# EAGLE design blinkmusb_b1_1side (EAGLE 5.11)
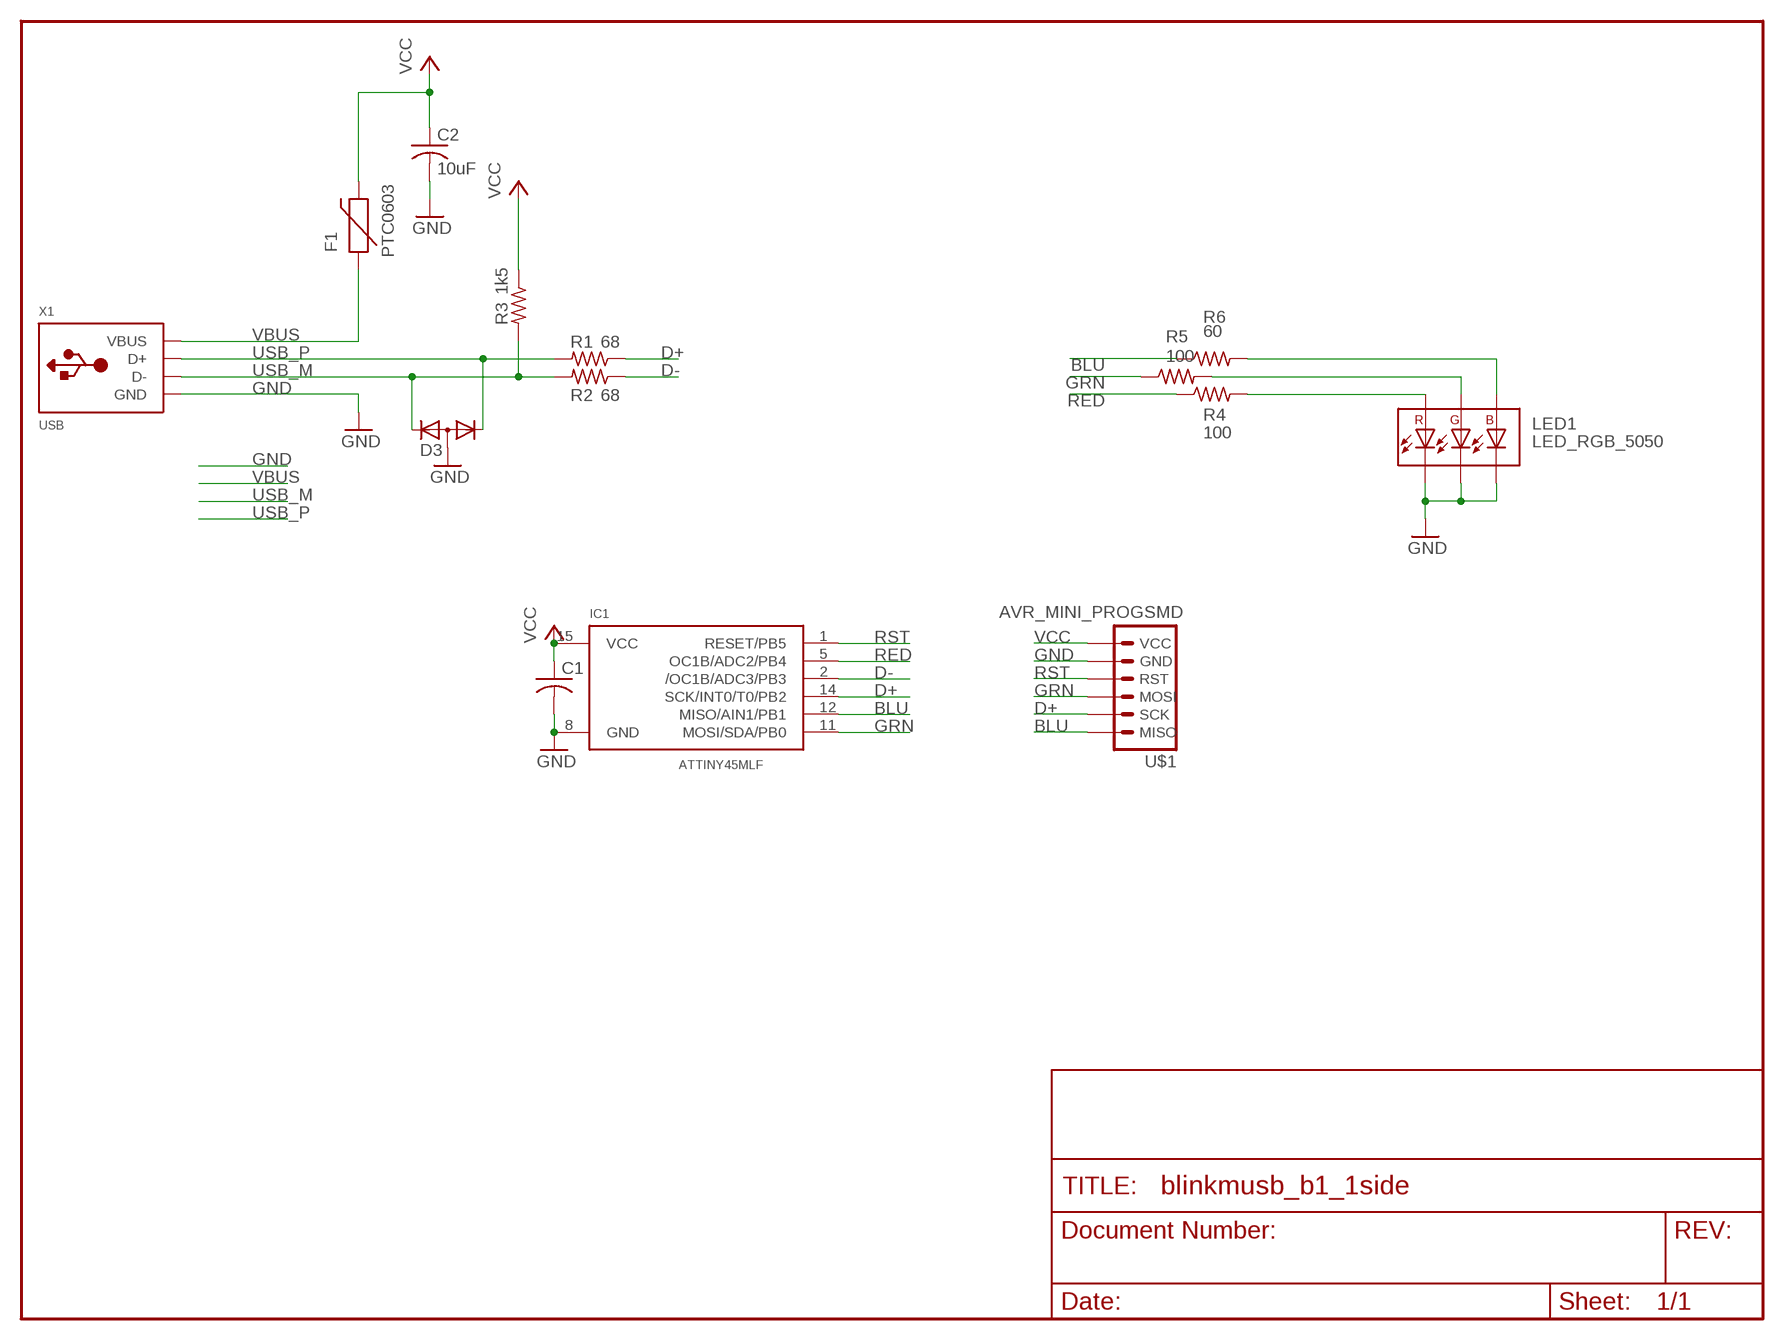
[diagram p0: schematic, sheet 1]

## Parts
C1  C-USC0603  [C0603]
C2  10uF  C-USC0805  [C0805]
D3  DIODE-2CA|ACSOT23  [SOT23]
F1  PTC0603  [0603]
IC1  ATTINY45MLF  [MLF20]
LED1  LED_RGB_5050  [LED_5050]
R1  68  R-US_R0603  [R0603]
R2  68  R-US_R0603  [R0603]
R3  1k5  R-US_R0603  [R0603]
R4  100  R-US_R0603  [R0603]
R5  100  R-US_R0603  [R0603]
R6  60  R-US_R0603  [R0603]
U$1  AVR_MINI_PROGSMD  [AVR_MINI_PROG]
X1  USB  [MOLEX-48037-1000]

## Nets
BLU: IC1.12(MISO/AIN1/PB1) R6.1 U$1.6(MISO)
D+: IC1.14(SCK/INT0/T0/PB2) R1.1 U$1.5(SCK)
D-: IC1.2(/OC1B/ADC3/PB3) R2.1
GND: C1.2 C2.2 D3.3(A) IC1.8(GND) LED1.P$4(C2) LED1.P$5(C1) LED1.P$6(C0) U$1.2(GND) X1.4(GND)
GRN: IC1.11(MOSI/SDA/PB0) R5.1 U$1.4(MOSI)
RBLU: LED1.P$3(A2) R6.2
RED: IC1.5(OC1B/ADC2/PB4) R4.1
RGRN: LED1.P$2(A1) R5.2
RRED: LED1.P$1(A0) R4.2
RST: IC1.1(RESET/PB5) U$1.3(RST)
USB_M: D3.2(K2) R2.2 R3.2 X1.2(D-)
USB_P: D3.1(K1) R1.2 X1.3(D+)
VBUS: F1.1 X1.1(VBUS)
VCC: C1.1 C2.1 F1.2 IC1.15(VCC) R3.1 U$1.1(VCC)

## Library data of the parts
C1 C2 = rcl:C-US: CAPACITOR, American symbol
D3 = diode:DIODE-2CA|AC: Dual DIODE Cathode-Anode|Anode-Cathode
F1 = SparkFun-20110517:PTC: Resettable Fuse PTC
IC1 = todstuff:ATTINY45
LED1 = todstuff:LED_RGB_5050
R1-R6 = rcl:R-US_: RESISTOR, American symbol
U$1 = SparkFun-20110517:AVR_MINI_PROG
X1 = todstuff:USB

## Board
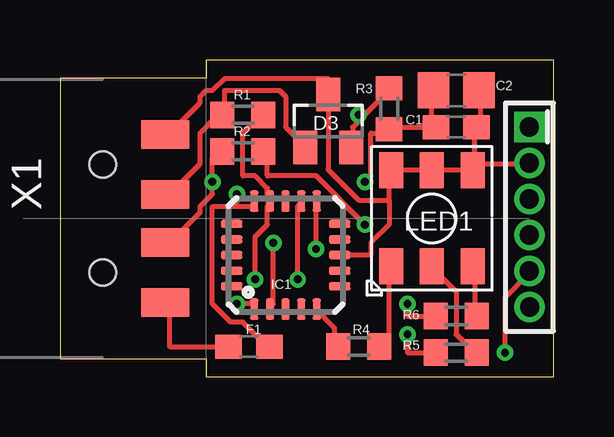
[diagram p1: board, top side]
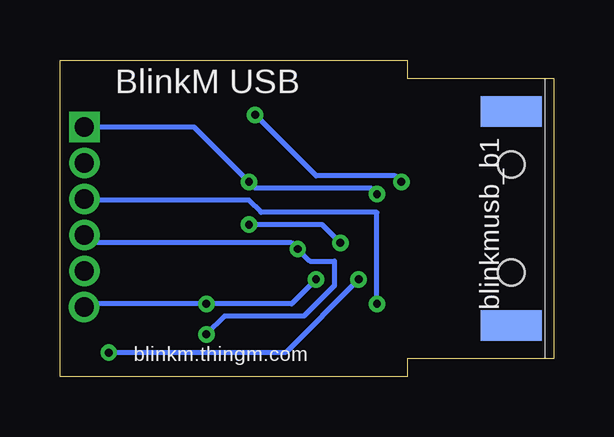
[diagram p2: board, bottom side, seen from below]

Size 20.57 x 13.21 mm. Coordinates in mm from the lower left corner, seen from the top.
Outline: 0,0.76 6.1,0.76 6.1,0 20.57,0 20.57,0.76 20.57,12.45 20.57,13.21 13.72,13.21 6.1,13.21 6.1,12.45 0,12.45 0,0.76
Copper layers (1*16): Top 0.0356mm / dielectric 1.5011mm / Bottom 0.0356mm
Design rules "LaenPCBOrder *": minimum track width 8mil, minimum drill 13mil, track to track 6mil, track to pad 8mil, pad to pad 8mil, via to via 8mil, smd to smd 6mil, copper to edge 15mil, drill to drill 8mil, minimum pad ring 7mil, minimum via ring 7mil, stop-mask expansion 4mil, vias tented up to drill 25mil, thermal gap 10mil
tRestrict: area -6.6,0 to 3.6,12.7
bRestrict: area -6.6,0 to 3.6,12.7

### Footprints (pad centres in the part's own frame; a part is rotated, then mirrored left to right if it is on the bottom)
C0603 = smd 1.1 x 1: 1 -0.85,0; 2 0.85,0
C0805 = smd 1.3 x 1.5: 1 -0.95,0; 2 0.95,0
SOT23 = smd 1 x 1.4: 1 -0.95,-1.1; 2 0.95,-1.1; 3 0,1.1
0603 = smd 1.1 x 1: 1 -0.85,0; 2 0.85,0
MLF20 = smd 0.9 x 0.35: 1 -2.25,1.3; 2 -2.25,0.65; 3 -2.25,0; 4 -2.25,-0.65; 5 -2.25,-1.3; 11 2.25,-1.3; 12 2.25,-0.65; 13 2.25,0; 14 2.25,0.65; 15 2.25,1.3 | smd 0.35 x 0.9: 6 -1.3,-2.25; 7 -0.65,-2.25; 8 0,-2.25; 9 0.65,-2.25; 10 1.3,-2.25; 16 1.3,2.25; 17 0.65,2.25; 18 0,2.25; 19 -0.65,2.25; 20 -1.3,2.25
LED_5050 = smd 1 x 1.5: P$1 1.7,2; P$2 0,2; P$3 -1.7,2; P$4 -1.7,-2; P$5 0,-2; P$6 1.7,-2
R0603 = smd 1 x 1.1: 1 -0.85,0; 2 0.85,0
AVR_MINI_PROG = drill 0.8 pad 1.27 square: 1 0,0 | drill 0.8 pad 1.27 round: 2 1.5,0; 3 3,0; 4 4.5,0; 5 6,0; 6 7.5,0.01
MOLEX-48037-1000 = smd 2 x 1.2: 1 2.6,-3.5; 2 2.6,-1; 3 2.6,1; 4 2.6,3.5 | smd 2.54 x 1.27 bottom: P$1 0,4.45; P$2 0,-4.45 | hole 1.1: 0,2.25; 0,-2.25

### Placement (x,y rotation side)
C1  16.51,10.41 0 top
C2  16.51,11.94 0 top
D3  11.18,10.67 0 top
F1  7.87,1.27 0 top
IC1  9.4,5.08 90 top
LED1  15.49,6.6 180 top
R1  7.62,10.92 180 top
R2  7.62,9.4 180 top
R3  13.72,11.18 90 top
R4  12.45,1.27 0 top
R5  16.51,1.02 0 top
R6  16.51,2.54 0 top
U$1  19.56,10.41 270 top
X1  1.78,6.6 0 top

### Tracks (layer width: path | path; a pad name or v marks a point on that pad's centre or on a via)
BLU  (via drill 0.33)
  Top 0.203: v9.91,4.06 9.91,7.11 IC1.12 | v14.48,3.05 14.48,2.54 15.49,2.54 R6.1
  Bottom 0.203: v9.91,4.06 10.92,3.05 v14.48,3.05 19.56,3.05 U$1.6
D+  (via drill 0.33)
  Top 0.203: R1.1 8.38,10.92 7.62,10.16 7.62,8.38 8.13,8.38 8.64,7.87 8.64,7.37 IC1.14 8.64,7.11 8.64,6.35 8.13,5.84 v8.13,4.06 | v18.54,1.02 18.54,3.3 19.56,4.32 U$1.5
  Bottom 0.203: v8.13,4.06 11.18,1.02 v18.54,1.02
D-  (via drill 0.33)
  Top 0.203: v8.89,5.59 8.89,3.05 IC1.2 | v12.7,6.35 10.67,8.38 8.64,8.38 8.64,9.4 R2.1
  Bottom 0.203: v8.89,5.59 9.65,6.35 v12.7,6.35
GND
  Top 0.203: C2.2 17.53,11.94 17.53,10.41 C1.2 17.27,10.41 17.27,8.89 | 13.72,7.37 13.72,8.38 LED1.P$6 13.97,8.64 15.49,8.64 | 13.72,7.37 13.72,6.35 12.95,5.59 12.95,5.08 11.68,5.08 IC1.8 | 13.72,7.37 12.45,7.37 11.18,8.64 11.18,11.68 D3.3 11.18,11.94 11.18,12.45 6.86,12.45 6.35,11.94 6.1,11.94 5.84,11.68 5.84,11.43 4.57,10.16 X1.4 | 15.49,8.64 LED1.P$5 15.49,8.64 | 15.49,8.64 17.02,8.64 LED1.P$4 | 17.27,8.89 17.27,8.64 LED1.P$4 | 17.27,8.89 19.56,8.89 U$1.2 | LED1.P$4 17.27,8.89
GRN  (via drill 0.33)
  Top 0.203: v10.67,5.33 10.67,7.11 IC1.11 | v14.48,1.78 14.48,1.02 15.49,1.02 R5.1
  Bottom 0.203: U$1.4 19.56,5.84 19.3,5.59 10.92,5.59 v10.67,5.33 10.16,4.83 9.14,4.83 9.14,3.81 10.41,2.54 13.72,2.54 v14.48,1.78
RBLU
  Top 0.203: R6.2 17.27,2.54 17.27,4.57 LED1.P$3
RED
  Top 0.203: IC1.5 10.67,2.79 11.43,2.03 11.43,1.27 R4.1
RGRN
  Top 0.203: R5.2 17.27,1.02 16.51,1.78 16.51,3.56 15.49,4.57 LED1.P$2
RRED
  Top 0.203: R4.2 13.46,1.27 13.72,1.52 13.72,4.57 LED1.P$1
RST  (via drill 0.33)
  Top 0.203: v7.37,3.05 8.13,3.05 IC1.1
  Bottom 0.203: v7.37,3.05 7.37,6.86 12.19,6.86 12.7,7.37 19.56,7.37 U$1.3
USB_M  (via drill 0.33)
  Top 0.203: 12.7,10.92 12.19,10.41 12.19,9.65 D3.2 | 12.7,10.92 13.72,11.94 R3.2 | R2.2 6.6,9.4 6.35,9.14 v6.35,8.13 6.35,7.62 5.84,7.11 5.84,6.86 4.57,5.59 X1.2 | v12.45,10.92 12.7,10.92
  Bottom 0.203: v12.45,10.92 9.91,8.38 6.6,8.38 v6.35,8.13
USB_P
  Top 0.203: X1.3 4.57,7.62 5.84,8.89 5.84,10.16 6.6,10.92 R1.2 6.86,10.92 6.86,11.94 9.14,11.94 9.4,11.68 9.4,10.41 10.16,9.65 D3.1
VBUS
  Top 0.203: F1.1 6.86,1.27 4.57,1.27 4.57,3.05 X1.1
VCC  (via drill 0.33)
  Top 0.203: 7.37,7.11 6.35,7.11 6.35,3.05 7.11,2.29 7.62,2.29 8.64,1.27 F1.2 | 7.37,7.11 8.13,7.11 IC1.15 | 15.49,10.41 13.72,10.41 R3.1 13.72,10.16 12.95,10.16 12.95,8.38 v12.7,8.13 | 15.49,10.41 C1.1 15.49,10.41 | 15.49,10.41 15.49,11.94 C2.1 | 7.37,7.11 v7.37,7.62
  Bottom 0.203: U$1.1 14.99,10.41 v12.7,8.13 12.45,7.87 7.62,7.87 v7.37,7.62

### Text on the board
bPlace: BlinkM USB | blinkmusb_b1 | blinkm.thingm.com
